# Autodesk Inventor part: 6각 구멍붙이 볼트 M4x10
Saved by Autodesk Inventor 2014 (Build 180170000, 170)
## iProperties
Created: 2026-04
Part Number: 6각 구멍붙이 볼트 M4x10
Material: 강철, 연강
Document SubType Name: Modeling
Designer: dg
Density: 7.86 g/cm^3
Appearance: 강철
Author: jhkim
Description: 6각머리 태핑 나사
Creation Date: 2026-03-27
Sending System: Autodesk Inventor 2026
Preprocessor: ST-DEVELOPER v20.1
Author: dg
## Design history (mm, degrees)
node "6각 구멍붙이 볼트 M4x101"
body "Solid1"
node "기준1"
